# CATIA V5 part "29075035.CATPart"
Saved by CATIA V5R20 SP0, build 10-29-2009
Part number: 29075035
Definition: NONE
Nomenclature: 29075035
Source: Unknown
Description: 29075035
Bounding box of the stored display mesh (mm): x -17.5 to 44.548, y -51.5 to 86.048, z -41.5 to 41.5
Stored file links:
  C:\Users\Utente\Desktop\IO LAVORO\3D X SITO CF\X SITO\PLASTICA\RF1\29075035.CATPart
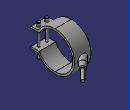
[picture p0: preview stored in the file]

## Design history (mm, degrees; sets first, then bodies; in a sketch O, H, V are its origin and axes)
Body1 "29075035" (main body)
  Solid1: solid without history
